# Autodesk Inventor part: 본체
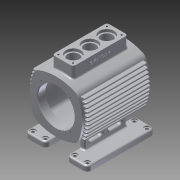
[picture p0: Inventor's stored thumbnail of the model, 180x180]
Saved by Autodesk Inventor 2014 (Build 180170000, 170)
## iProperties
Created: 2015-11
Part Number: 본체
Material: 알루미늄 6061
Document SubType Name: Modeling
Designer: mduedu
Density: 2.71 g/cm^3
Mass: 1542.17 g
Surface Area: 1694.56 cm^2
Volume: 569.067 cm^3
Appearance: 알루미늄 - 평지
Author: mduedu
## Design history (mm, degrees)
sketch "스케치2"
  geometry: L1 (0, 250)-(0, -250); L2 (250, 0)-(-250, 0); L3 (-50, 50)-(50, 50); L4 (50, 50)-(50, -50); L5 (50, -50)-(-50, -50); L6 (-50, -50)-(-50, 50); A1 r 90 centre (-40, 0) between (40.415, -40.415) and (40.415, 40.415); A2 r 90 centre (40, 0) between (-40.415, 40.415) and (-40.415, -40.415); A3 r 90 centre (0, -40) between (40.415, 40.415) and (-40.415, 40.415); A4 r 90 centre (0, 40) between (-40.415, -40.415) and (40.415, -40.415); 2 further points
  constraints: 12 end point, 8 point on circle, 4 centre point, 4 tangent, 3 perpendicular, 2 horizontal alignment, 2 midpoint, 2 parallel, 2 symmetric about line, 1 coincident, 1 equal radius, 1 horizontal, 1 vertical, 1 vertical alignment, 2 other
  dimensions: "d6" = 500 distance of L1.start L1.end; "d8" = 500 distance of L2.start L2.end; "d9" = 100 distance of L3.end L4.end; "d11" = 90 radius of A3
extrude "돌출1" new body sketch "스케치2" stored distance "d12" = 130; taper "d13" = 0 deg
sketch "스케치3"
  geometry: A1 r 90 centre (40, 0) between (-40.415, 40.415) and (-40.415, -40.415) reference; 2 further points
  constraints: 1 point on circle
fillet "모깎기6" dims "d30" = 15
feature "쉘1" dims "d31" = 15, "d32" = 6, "d33" = 15
sketch "스케치4"
  geometry: L1 (60, -57)-(-60, -57); L2 (-65, 40.415)-(-65, -40.415) reference; L3 (65, -40.415)-(65, 40.415) reference; L4 (-60, -57)-(-60, -45); L5 (60, -57)-(60, -45); L6 (-65, -50)-(65, -50) reference; L7 (-60, -45)-(60, -45); 2 further points
  constraints: 8 end point, 2 parallel, 1 horizontal
  dimensions: "d16" = 5 distance between parallel lines of L7 L6; "d17" = 12 distance of L1.start L5.end; "d23" = 5 distance between parallel lines of L4 L2; "d24" = 5 distance between parallel lines of L5 L3
extrude "돌출2" new body sketch "스케치4" stored distance "d18" = 3; taper "d19" = 0 deg
fillet "모깎기1" dims "d20" = 3
fillet "모깎기4" dims "d25" = 1
sketch "스케치5"
  geometry: C1 r 35 at (0, 0); 1 further point
  constraints: 1 centre point, 1 coincident
  dimensions: "d34" = 70 diameter of C1
extrude "돌출3" cut sketch "스케치5" stored distance "d36" = 3; taper "d37" = 0 deg
feature "결합1"
  node "솔리드2"
fillet "모깎기7" dims "d38" = 1
fillet "모깎기8" dims "d39" = 1
node "작업 평면1"
sketch "스케치6"
  geometry: L1 (-65, -60)-(65, -60); L2 (65, -60)-(65, 60); L3 (65, 60)-(-65, 60); L4 (-65, 60)-(-65, -60); L5 (-65, -60)-(65, 60); L6 (65, -60)-(-65, 60); 1 further point
  constraints: 12 end point, 2 midpoint, 2 parallel, 1 horizontal, 1 perpendicular
  dimensions: "d41" = 120 distance of L3.end L1.start; "d43" = 130 distance of L2.end L3.end
extrude "돌출4" join sketch "스케치6" distance "d44" = 10; taper "d45" = 0 deg
sketch "스케치8"
  geometry: L1 (-60, -70)-(60, -70) reference; L2 (0, -50)-(0, -70); L3 (-30, -44.853)-(-30, -70); L4 (30, -44.853)-(30, -70); L5 (-30, -70)-(30, -70); A1 r 90 centre (0, 40) between (-34.941, -42.941) and (34.941, -42.941) reference; A2 r 90 centre (0, 40) between (-30, -44.853) and (30, -44.853); 1 further point
  constraints: 8 end point, 5 point on circle, 2 perpendicular, 2 symmetric about line, 1 centre point, 1 midpoint, 1 point on line
  dimensions: "d48" = 60 distance between parallel lines of L4 L3
extrude "돌출5" join sketch "스케치8" stored distance "d50" = 80; taper "d51" = 0 deg
sketch "스케치9"
  geometry: L1 (-30, -44.853)-(-30, -70) reference; L2 (30, -70)-(30, -44.853) reference; L3 (-20, -47.75)-(-20, -80); L4 (20, -80)-(20, -47.75); L5 (-48.917, -80)-(48.917, -80) reference; A1 r 90 centre (0, 40) between (-34.941, -42.941) and (34.941, -42.941) reference; 1 further point
  constraints: 4 end point, 2 parallel, 2 point on circle, 2 point on line
  dimensions: "d52" = 10 distance between parallel lines of L2 L4; "d54" = 10 distance between parallel lines of L1 L3 (derived)
extrude "돌출6" cut sketch "스케치9" stored distance "d55" = 80; taper "d56" = 0 deg
fillet "모깎기9" dims "d57" = 8
sketch "스케치10"
  geometry: A1 r 8 centre (-57, 52) between (-57, 60) and (-65, 52) reference; A2 r 8 centre (57, 52) between (65, 52) and (57, 60) reference; A3 r 8 centre (57, 28) between (57, 20) and (65, 28) reference; A4 r 8 centre (-57, 28) between (-65, 28) and (-57, 20) reference; A5 r 8 centre (-57, -28) between (-57, -20) and (-65, -28) reference; A6 r 8 centre (-57, -52) between (-65, -52) and (-57, -60) reference; A7 r 8 centre (57, -52) between (57, -60) and (65, -52) reference; A8 r 8 centre (57, -28) between (65, -28) and (57, -20) reference; 1 further point
hole "구멍1" sketch "스케치10" at (-57, 52), (57, 52), (57, 28), (-57, 28), (-57, -28), (-57, -52), (57, -52), (57, -28) diameter "d58" = 6; stored, may be unused: countersink angle "d62" = 90 deg, drill point angle "d64" = 118 deg; dims "d59" = 6, "d60" = 10, "d61" = 2, "d63" = 8
fillet "모깎기10" dims "d65" = 3
fillet "모깎기11" dims "d66" = 3
fillet "모깎기12" dims "d67" = 3
sketch "스케치11" dims "d72" = 25
  geometry: L1 (65, -50)-(-65, -50) reference; L2 (-80.5, -80)-(80.5, -80) reference; L3 (0, -50)-(0, -80); L4 (-27, -54)-(-10, -54); L5 (-10, -54)-(-10, -62); L6 (-10, -62)-(-27, -62); L7 (-27, -62)-(-27, -54); 3 further points
  constraints: 10 end point, 4 midpoint, 2 parallel, 2 perpendicular, 2 vertical alignment, 1 horizontal, 4 other
  dimensions: "d68" = 8 distance between parallel lines of L6 L4; "d71" = 8 distance from line of point (-27, -58) L1; "d73" = 6 dimension on L3
extrude "돌출7" cut sketch "스케치11" stored distance "d74" = 80; taper "d75" = 0 deg
fillet "모깎기13" dims "d76" = 3
fillet "모깎기14" dims "d78" = 3
sketch "스케치12"
  geometry: L1 (0, 0)-(28.284, 28.284); L2 (0, 0)-(40, 0); A1 r 40 centre (0, 0) between (28.284, 28.284) and (40, 0); 2 further points
  constraints: 4 end point, 2 coincident, 2 point on circle, 1 centre point, 1 horizontal
  dimensions: "d79" = 80 diameter of A1; "d80" = 45 deg angle of L2 L1
hole "구멍2" sketch "스케치12" at (28.284, 28.284) diameter "d82" = 3.242; stored, may be unused: countersink angle "d86" = 90 deg, drill point angle "d88" = 118 deg; dims "d83" = 9, "d84" = 10, "d85" = 2, "d87" = 11
node "작업 평면2"
sketch "스케치13"
  geometry: L1 (-52.5, -20)-(52.5, -20); L2 (52.5, -20)-(52.5, 20); L3 (52.5, 20)-(-52.5, 20); L4 (-52.5, 20)-(-52.5, -20); L5 (-52.5, -20)-(52.5, 20); L6 (52.5, -20)-(-52.5, 20); 1 further point
  constraints: 12 end point, 2 midpoint, 2 parallel, 1 horizontal, 1 perpendicular
  dimensions: "d93" = 105 distance of L2.end L3.end; "d95" = 40 distance of L1.end L2.end
extrude "돌출8" join sketch "스케치13" stored distance "d96" = 80; taper "d97" = 0 deg
fillet "모깎기15" dims "d98" = 5
fillet "모깎기16" dims "d99" = 3
sketch "스케치14"
  geometry: L1 (-52.5, 15)-(-52.5, -15) reference; L2 (52.5, -15)-(52.5, 15) reference; L3 (-52.5, 0)-(52.5, 0); 4 further points
  constraints: 2 end point, 2 midpoint, 2 point on line, 1 coincident
  dimensions: "d100" = 32 distance of point (-32, 0) point (0, 0); "d102" = 32 distance of point (32, 0) point (0, 0) (derived)
hole "구멍3" sketch "스케치14" at (-32, 0), (0, 0), (32, 0) diameter "d103" = 22; stored, may be unused: countersink angle "d107" = 90 deg, drill point angle "d109" = 118 deg; dims "d104" = 8, "d105" = 28, "d106" = 5, "d108" = 10
sketch "스케치15"
  geometry: L1 (46.5, -14)-(-46.5, -14); L2 (-46.5, -14)-(-46.5, 14); L3 (-46.5, 14)-(46.5, 14); L4 (46.5, 14)-(46.5, -14); L5 (46.5, -14)-(-46.5, 14); L6 (-46.5, -14)-(46.5, 14); L7 (47.5, 20)-(-47.5, 20) reference; L8 (-52.5, 15)-(-52.5, -15) reference; 5 further points
  constraints: 12 end point, 4 coincident, 2 midpoint, 2 parallel, 1 horizontal, 1 perpendicular
  dimensions: "d110" = 6 distance between parallel lines of L3 L7; "d111" = 6 distance between parallel lines of L2 L8
hole "구멍4" sketch "스케치15" at (-46.5, 14), (46.5, 14), (46.5, -14), (-46.5, -14) diameter "d112" = 3.242; stored, may be unused: countersink angle "d116" = 90 deg, drill point angle "d118" = 118 deg; dims "d113" = 10, "d114" = 28, "d115" = 5, "d117" = 13
sketch "스케치16"
  geometry: L1 (33.5, 0)-(61.5, 0) reference; L2 (104.5, -150)-(-9.5, -150) reference; L3 (47.5, 0)-(47.5, -150); 2 further points
  constraints: 2 end point, 2 midpoint, 1 point on line, 1 other
  dimensions: "d122" = 11 distance from line of point (47.5, -11) L1
feature "엠보싱2" sketch "스케치16" dims "d16" = 5, "d17" = 12, "d23" = 5, "d24" = 5, "d123" = 0.5, "d124" = 0
chamfer "모따기1" distance "d125" = 1; stored, may be unused: second distance "d126" = 2, angle "d127" = 45 deg
node "솔리드1"
pattern_linear "직사각형 패턴1" dims "d29" = 7
mirror "대칭1"
mirror "대칭2"
pattern_circular "원형 패턴1" dims angle "d90" = 360 deg
mirror "대칭3"
